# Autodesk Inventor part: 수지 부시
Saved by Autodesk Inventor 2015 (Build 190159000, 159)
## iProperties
Created: 2024-11
Part Number: 수지 부시
Material: 일반
Document SubType Name: Modeling
Designer: 102-5
Density: 1 g/cm^3
Appearance: 기본값
Author: 102-5
Author: jhkim
Creation Date: 2024-10-25
Sending System: Autodesk Inventor 2025
Preprocessor: ST-DEVELOPER v20
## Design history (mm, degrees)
node "수지 부시1"
node "솔리드1"
node "기준1"
